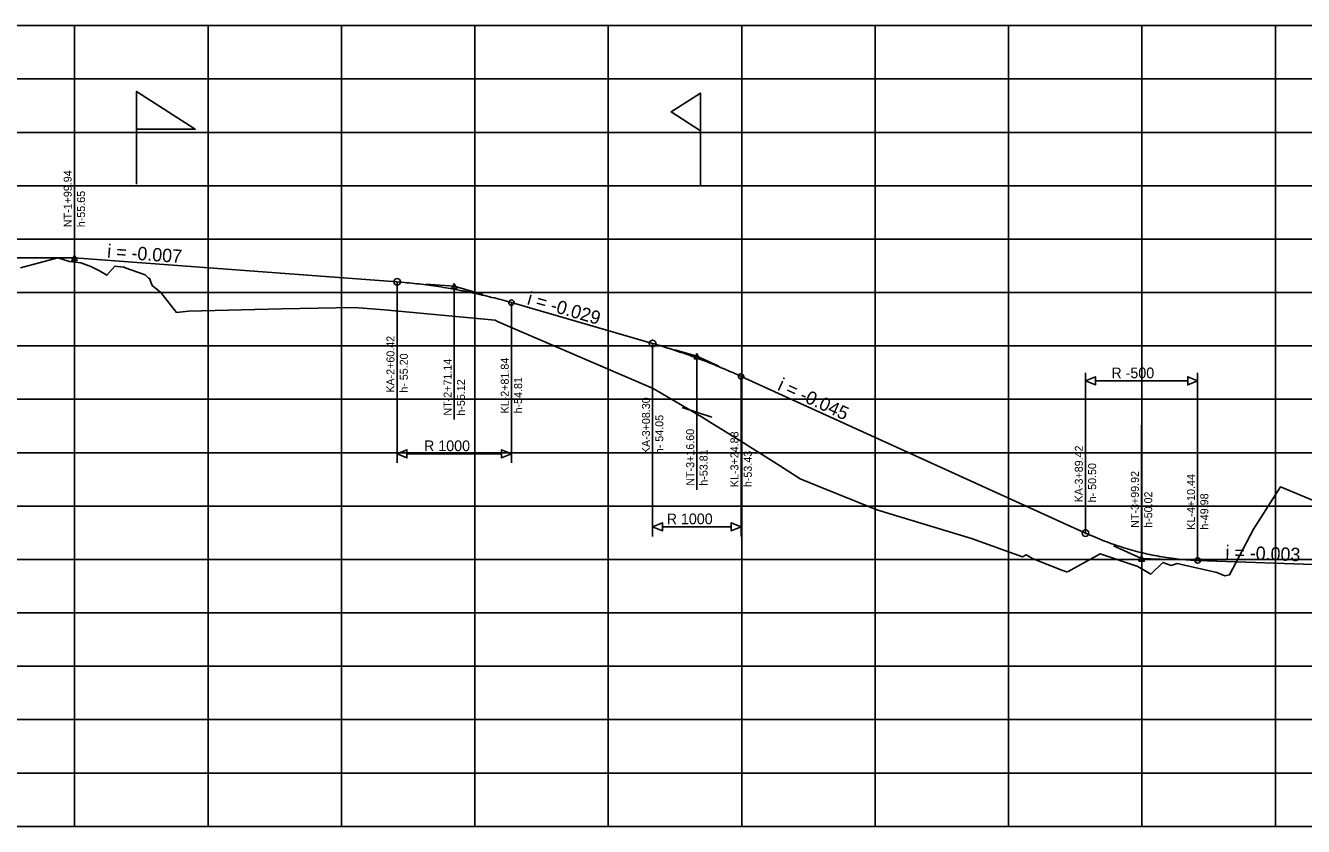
# Model space of a CAD drawing. Extents: x 655100 to 703495, y 6445581 to 6476602.
# Drawn here: x 669500.1 to 669739.6, y 6465869.6 to 6466019.6 of the extents above; entities that cross this region are included whole.
import ezdxf

# ---------------------------------------------------------------- set-up
doc = ezdxf.new("R2010")
doc.units = 0
for name, color, linetype in [('1_truup proj', 7, 'Continuous'), ('Level 25', 7, 'Continuous'), ('Level 6', 7, 'Continuous'), ('Profile', 7, 'Continuous'), ('Prop Vertical Alignment', 7, 'Continuous')]:
    doc.layers.add(name, color=color, linetype=linetype)

msp = doc.modelspace()

# ---------------------------------------------------------------- linework, layer by layer
at = {"layer": '1_truup proj'}
msp.add_line((669628.69, 6465946.24), (669623.12, 6465948.01), dxfattribs=at)
at = {"layer": 'Level 25'}
for points in [[(669520.9, 6465989.88), (669520.9, 6466007.24), (669531.91, 6466000.16), (669520.89, 6466000.15)], [(669626.57, 6465989.57), (669626.57, 6466006.92), (669621.07, 6466003.39), (669626.58, 6465999.84)]]:
    msp.add_lwpolyline(points, dxfattribs=at)
at = {"layer": 'Level 6'}
msp.add_lwpolyline([(669499.16, 6465974.21), (669506.12, 6465976.05), (669508.33, 6465975.36), (669510.49, 6465975.16), (669512.34, 6465974.44), (669513.93, 6465973.65), (669515.36, 6465972.81), (669516.85, 6465974.5), (669518.42, 6465974.35), (669518.58, 6465974.3), (669518.78, 6465974.22), (669522.5, 6465972.86), (669523.11, 6465972.28), (669523.32, 6465972.22), (669523.83, 6465970.91), (669525.43, 6465969.59), (669528.37, 6465965.84), (669530.66, 6465966.11), (669548.06, 6465966.5), (669561.69, 6465966.76), (669567.34, 6465966.35), (669588.1, 6465964.37), (669588.4, 6465964.23), (669589.11, 6465963.89), (669617.68, 6465951.59), (669626.89, 6465946.2), (669628.28, 6465945.38), (669634.13, 6465941.73), (669641.37, 6465937.16), (669645.27, 6465934.68), (669648.62, 6465933.33), (669659.61, 6465928.87), (669677.36, 6465923.49), (669686.95, 6465920.09), (669687.63, 6465920.44), (669688.92, 6465919.72), (669694.28, 6465917.58), (669695.18, 6465917.28), (669695.22, 6465917.28), (669695.46, 6465917.35), (669701.47, 6465920.62), (669708.52, 6465918.27), (669710.97, 6465916.83), (669713.19, 6465919.01), (669714.77, 6465918.47), (669715.88, 6465918.81), (669723.36, 6465917.12), (669724.86, 6465916.54), (669725.74, 6465916.69), (669730.22, 6465925.23), (669735.24, 6465933.15), (669741.27, 6465930.69)], dxfattribs=at)
at = {"layer": 'Profile'}
for p, q in [((669309.3, 6466019.57), (670209.3, 6466019.57)), ((669309.3, 6466019.57), (670209.3, 6466019.57)), ((669509.3, 6465869.57), (669509.3, 6466019.57)), ((669534.3, 6465869.57), (669534.3, 6466019.57)), ((669559.3, 6465869.57), (669559.3, 6466019.57)), ((669584.3, 6465869.57), (669584.3, 6466019.57)), ((669609.3, 6465869.57), (669609.3, 6466019.57)), ((669634.3, 6465869.57), (669634.3, 6466019.57)), ((669659.3, 6465869.57), (669659.3, 6466019.57)), ((669684.3, 6465869.57), (669684.3, 6466019.57)), ((669709.3, 6465869.57), (669709.3, 6466019.57)), ((669734.3, 6465869.57), (669734.3, 6466019.57)), ((669309.3, 6466009.57), (670209.3, 6466009.57)), ((669309.3, 6465999.57), (670209.3, 6465999.57)), ((669309.3, 6465989.57), (670209.3, 6465989.57)), ((669309.3, 6465979.57), (670209.3, 6465979.57)), ((669309.3, 6465969.57), (670209.3, 6465969.57)), ((669309.3, 6465959.57), (670209.3, 6465959.57)), ((669309.3, 6465949.57), (670209.3, 6465949.57)), ((669309.3, 6465939.57), (670209.3, 6465939.57)), ((669309.3, 6465929.57), (670209.3, 6465929.57)), ((669309.3, 6465919.57), (670209.3, 6465919.57)), ((669309.3, 6465909.57), (670209.3, 6465909.57)), ((669309.3, 6465899.57), (670209.3, 6465899.57)), ((669309.3, 6465889.57), (670209.3, 6465889.57)), ((669309.3, 6465879.57), (670209.3, 6465879.57)), ((669309.3, 6465869.57), (670209.3, 6465869.57))]:
    msp.add_line(p, q, dxfattribs=at)
at = {"layer": 'Prop Vertical Alignment'}
for p, q in [((669509.25, 6465981.06), (669509.25, 6466001.06)), ((669509.25, 6465976.06), (669509.25, 6465981.06)), ((669470.34, 6465976.06), (669509.25, 6465976.06)), ((669509.25, 6465976.06), (669569.73, 6465971.56)), ((669569.73, 6465971.56), (669569.73, 6465966.56)), ((669569.73, 6465971.56), (669569.73, 6465937.68)), ((669575.08, 6465971.16), (669580.44, 6465970.77)), ((669580.44, 6465970.77), (669585.79, 6465969.22)), ((669580.44, 6465970.77), (669580.44, 6465965.77)), ((669591.15, 6465967.68), (669591.15, 6465962.68)), ((669591.15, 6465967.68), (669617.61, 6465960.04)), ((669591.15, 6465967.68), (669591.15, 6465937.68)), ((669569.73, 6465966.56), (669569.73, 6465950.06)), ((669580.44, 6465965.77), (669580.44, 6465945.77)), ((669591.15, 6465962.68), (669591.15, 6465946.18)), ((669617.61, 6465960.04), (669617.61, 6465955.04)), ((669617.61, 6465960.04), (669617.61, 6465923.87)), ((669621.75, 6465958.84), (669625.9, 6465957.64)), ((669625.9, 6465957.64), (669630.04, 6465955.76)), ((669625.9, 6465957.64), (669625.9, 6465952.64)), ((669617.61, 6465955.04), (669617.61, 6465938.54)), ((669625.9, 6465952.64), (669625.9, 6465932.64)), ((669634.19, 6465953.87), (669634.19, 6465948.87)), ((669634.19, 6465953.87), (669698.72, 6465924.52)), ((669634.19, 6465953.87), (669634.19, 6465923.87)), ((669698.72, 6465924.52), (669698.72, 6465954.52)), ((669719.74, 6465919.39), (669719.74, 6465954.52)), ((669634.19, 6465948.87), (669634.19, 6465932.37)), ((669698.72, 6465929.52), (669698.72, 6465946.02)), ((669709.23, 6465924.75), (669709.23, 6465944.75)), ((669719.74, 6465924.39), (669719.74, 6465940.89)), ((669698.72, 6465924.52), (669698.72, 6465929.52)), ((669709.23, 6465919.75), (669709.23, 6465924.75)), ((669719.74, 6465919.39), (669719.74, 6465924.39)), ((669703.98, 6465922.14), (669709.23, 6465919.75)), ((669709.23, 6465919.75), (669714.49, 6465919.57)), ((669719.74, 6465919.39), (669771.38, 6465917.64))]:
    msp.add_line(p, q, dxfattribs=at)
for points in [[(669509.25, 6465976.56), (669509.75, 6465975.56), (669508.75, 6465975.56)], [(669580.44, 6465971.27), (669580.94, 6465970.27), (669579.94, 6465970.27)], [(669625.9, 6465958.14), (669626.4, 6465957.14), (669625.4, 6465957.14)], [(669698.72, 6465953.02), (669700.57, 6465952.26), (669700.57, 6465953.79)], [(669719.74, 6465953.02), (669717.9, 6465953.79), (669717.9, 6465952.26)], [(669569.73, 6465939.37), (669571.57, 6465938.6), (669571.57, 6465940.14)], [(669591.15, 6465939.37), (669589.3, 6465940.14), (669589.3, 6465938.6)], [(669617.61, 6465925.68), (669619.45, 6465924.92), (669619.45, 6465926.45)], [(669634.19, 6465925.68), (669632.34, 6465926.45), (669632.34, 6465924.92)], [(669709.23, 6465920.25), (669709.73, 6465919.25), (669708.73, 6465919.25)]]:
    msp.add_lwpolyline(points, close=True, dxfattribs=at)
for points in [[(669569.73, 6465971.56), (669570.18, 6465971.53), (669570.64, 6465971.49), (669571.09, 6465971.45), (669571.55, 6465971.41), (669572.01, 6465971.37), (669572.46, 6465971.32), (669572.92, 6465971.27), (669573.37, 6465971.22), (669573.83, 6465971.17), (669574.29, 6465971.12), (669574.74, 6465971.06), (669575.2, 6465971.01), (669575.65, 6465970.95), (669576.11, 6465970.88), (669576.56, 6465970.82), (669577.02, 6465970.75), (669577.48, 6465970.69), (669577.93, 6465970.62), (669578.39, 6465970.54), (669578.84, 6465970.47), (669579.3, 6465970.39), (669579.76, 6465970.31), (669580.21, 6465970.23), (669580.67, 6465970.15), (669581.12, 6465970.07), (669581.58, 6465969.98), (669582.03, 6465969.89), (669582.49, 6465969.8), (669582.95, 6465969.71), (669583.4, 6465969.61), (669583.86, 6465969.51), (669584.31, 6465969.41), (669584.77, 6465969.31), (669585.22, 6465969.21), (669585.68, 6465969.1), (669586.14, 6465969), (669586.59, 6465968.89), (669587.05, 6465968.77), (669587.5, 6465968.66), (669587.96, 6465968.55), (669588.41, 6465968.43), (669588.87, 6465968.31), (669589.33, 6465968.18), (669589.78, 6465968.06), (669590.24, 6465967.93), (669590.69, 6465967.81), (669591.15, 6465967.68)], [(669617.61, 6465960.04), (669617.96, 6465959.94), (669618.31, 6465959.83), (669618.67, 6465959.73), (669619.02, 6465959.62), (669619.37, 6465959.51), (669619.72, 6465959.4), (669620.08, 6465959.29), (669620.43, 6465959.18), (669620.78, 6465959.07), (669621.14, 6465958.96), (669621.49, 6465958.84), (669621.84, 6465958.73), (669622.19, 6465958.61), (669622.55, 6465958.49), (669622.9, 6465958.37), (669623.25, 6465958.25), (669623.61, 6465958.13), (669623.96, 6465958), (669624.31, 6465957.88), (669624.66, 6465957.75), (669625.02, 6465957.62), (669625.37, 6465957.5), (669625.72, 6465957.37), (669626.08, 6465957.23), (669626.43, 6465957.1), (669626.78, 6465956.97), (669627.13, 6465956.83), (669627.49, 6465956.7), (669627.84, 6465956.56), (669628.19, 6465956.42), (669628.55, 6465956.28), (669628.9, 6465956.14), (669629.25, 6465956), (669629.6, 6465955.86), (669629.96, 6465955.71), (669630.31, 6465955.56), (669630.66, 6465955.42), (669631.01, 6465955.27), (669631.37, 6465955.12), (669631.72, 6465954.97), (669632.07, 6465954.81), (669632.43, 6465954.66), (669632.78, 6465954.51), (669633.13, 6465954.35), (669633.48, 6465954.19), (669633.84, 6465954.03), (669634.19, 6465953.87)], [(669700.57, 6465953.02), (669717.9, 6465953.02)], [(669571.57, 6465939.37), (669589.3, 6465939.37)], [(669619.45, 6465925.68), (669632.34, 6465925.68)], [(669698.72, 6465924.52), (669699.17, 6465924.32), (669699.62, 6465924.13), (669700.07, 6465923.93), (669700.51, 6465923.74), (669700.96, 6465923.56), (669701.41, 6465923.38), (669701.85, 6465923.2), (669702.3, 6465923.03), (669702.75, 6465922.86), (669703.19, 6465922.69), (669703.64, 6465922.53), (669704.09, 6465922.37), (669704.54, 6465922.22), (669704.98, 6465922.07), (669705.43, 6465921.92), (669705.88, 6465921.78), (669706.32, 6465921.65), (669706.77, 6465921.51), (669707.22, 6465921.38), (669707.67, 6465921.26), (669708.11, 6465921.14), (669708.56, 6465921.02), (669709.01, 6465920.91), (669709.46, 6465920.8), (669709.9, 6465920.69), (669710.35, 6465920.59), (669710.8, 6465920.49), (669711.24, 6465920.4), (669711.69, 6465920.31), (669712.14, 6465920.23), (669712.59, 6465920.14), (669713.03, 6465920.07), (669713.48, 6465919.99), (669713.93, 6465919.93), (669714.38, 6465919.86), (669714.82, 6465919.8), (669715.27, 6465919.74), (669715.72, 6465919.69), (669716.17, 6465919.64), (669716.61, 6465919.59), (669717.06, 6465919.55), (669717.51, 6465919.52), (669717.96, 6465919.48), (669718.4, 6465919.45), (669718.85, 6465919.43), (669719.3, 6465919.41), (669719.74, 6465919.39)]]:
    msp.add_lwpolyline(points, dxfattribs=at)
for centre, radius in [((669569.73, 6465971.56), 0.625), ((669591.15, 6465967.68), 0.5), ((669617.61, 6465960.04), 0.625), ((669634.19, 6465953.87), 0.5), ((669698.72, 6465924.52), 0.625), ((669719.74, 6465919.39), 0.5)]:
    msp.add_circle(centre, radius, dxfattribs=at)

# ---------------------------------------------------------------- texts
for s, height, rotation, p in [('NT-1+99.94', 1.5, 90, (669508.75, 6465981.81)), ('h-55.65', 1.5, 90, (669511.25, 6465981.81)), ('i = -0.007', 2.5, 355.7506, (669515.33, 6465976.11)), ('i = -0.029', 2.5, 343.8999, (669593.93, 6465967.39)), ('KA-2+60.42', 1.5, 90, (669569.23, 6465950.81)), ('h- 55.20', 1.5, 90, (669571.73, 6465950.81)), ('NT-2+71.14', 1.5, 90, (669579.94, 6465946.52)), ('KL-2+81.84', 1.5, 90, (669590.65, 6465946.93)), ('h-55.12', 1.5, 90, (669582.44, 6465946.52)), ('h-54.81', 1.5, 90, (669593.15, 6465946.93)), ('i = -0.045', 2.5, 335.5436, (669640.85, 6465951.39)), ('KA-3+08.30', 1.5, 90, (669617.11, 6465939.29)), ('h- 54.05', 1.5, 90, (669619.61, 6465939.29)), ('NT-3+16.60', 1.5, 90, (669625.4, 6465933.39)), ('KL-3+24.88', 1.5, 90, (669633.69, 6465933.12)), ('KA-3+89.42', 1.5, 90, (669698.22, 6465930.27)), ('h-53.81', 1.5, 90, (669627.9, 6465933.39)), ('h-53.43', 1.5, 90, (669636.19, 6465933.12)), ('h- 50.50', 1.5, 90, (669700.72, 6465930.27)), ('NT-3+99.92', 1.5, 90, (669708.73, 6465925.5)), ('KL-4+10.44', 1.5, 90, (669719.24, 6465925.14)), ('h-50.02', 1.5, 90, (669711.23, 6465925.5)), ('h-49.98', 1.5, 90, (669721.74, 6465925.14)), ('i = -0.003', 2.5, 358.0565, (669724.92, 6465919.71))]:
    msp.add_text(s, height=height, rotation=rotation, dxfattribs=at).set_placement(p)
for s, p in [('R -500', (669703.57, 6465953.52)), ('R 1000', (669574.77, 6465939.87)), ('R 1000', (669620.24, 6465926.18))]:
    msp.add_text(s, height=2, dxfattribs=at).set_placement(p)

doc.saveas('drawing.dxf')
